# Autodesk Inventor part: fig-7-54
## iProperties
Shininess: 77.0
Length Units: 11269
Angle Units: 11279
Time Units: 11290
Mass Units: 11283
Length Display Precision: 3
Angle Display Precision: 2
Created: 2002-01
Part Number: fig-7-54
Document SubType Name: Modeling
Designer: ***
Density: 0.0
Volumn: 0.0
Area: 0.0
PropertySet Name: Model Information
Control State: 0
Master: False
Checked Out: False
Author: ***
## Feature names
1. Extrusion1
